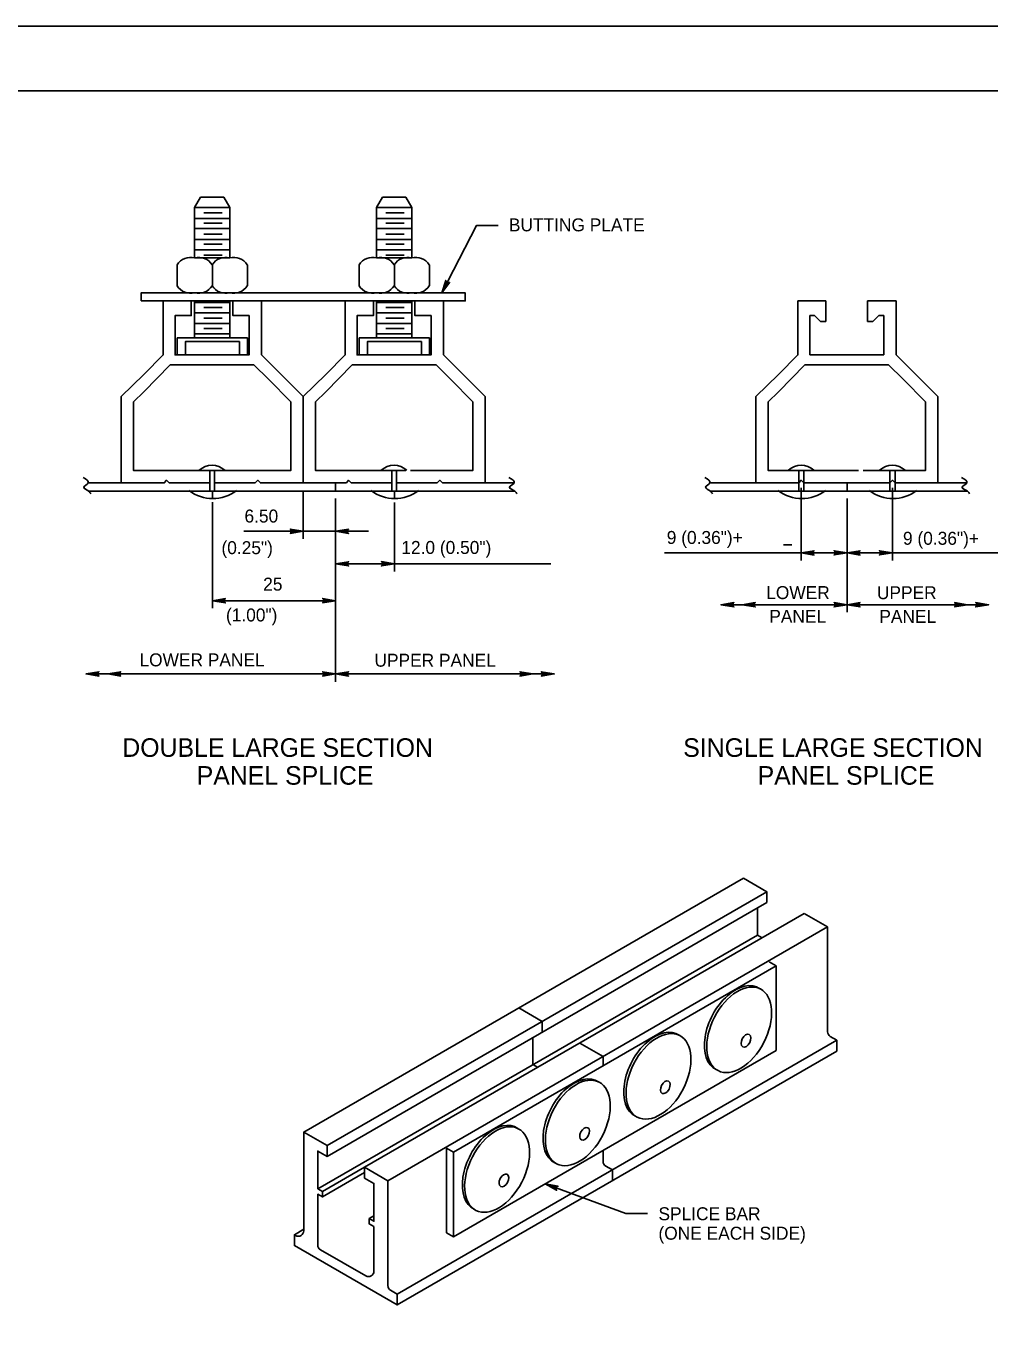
# Model space of a CAD drawing. Extents: x 650495 to 652241, y 298458 to 299646.
# Drawn here: x 651581.9 to 651805, y 299343.6 to 299645.6 of the extents above; entities that cross this region are included whole.
import ezdxf

# ---------------------------------------------------------------- set-up
doc = ezdxf.new("R2010")
doc.units = 0
for name, color, linetype in [('1', 7, 'Continuous'), ('2', 7, 'Continuous'), ('3', 7, 'Continuous'), ('PLT-BNDY', 7, 'Continuous')]:
    doc.layers.add(name, color=color, linetype=linetype)

# ---------------------------------------------------------------- blocks, each defined once
blk = doc.blocks.new('RARROW')
at = {"layer": '3'}
blk.add_lwpolyline([(-2.2695, 0.285), (-2.184875, 0.12075), (0, 0), (-2.2695, 0.285), (-2.38575, 0.384625), (0, 0), (-2.183125, -0.108), (-2.262875, -0.2705), (0, 0), (-2.38575, -0.379125), (-2.262875, -0.2705)], dxfattribs=at)

msp = doc.modelspace()

# ---------------------------------------------------------------- linework, layer by layer
at = {"layer": '1'}
msp.add_line((651376.31, 299630.63), (652162.31, 299630.63), dxfattribs=at)
at = {"layer": '2'}
for p, q in [((651620.9, 299603.62), (651622.28, 299606)), ((651622.28, 299606), (651627.65, 299606)), ((651629.03, 299603.62), (651627.65, 299606)), ((651663.03, 299603.62), (651664.4, 299606)), ((651664.4, 299606), (651669.78, 299606)), ((651671.15, 299603.62), (651669.78, 299606)), ((651620.9, 299603.62), (651629.03, 299603.62)), ((651620.9, 299603.62), (651620.9, 299601.12)), ((651620.9, 299592), (651620.9, 299603.62)), ((651629.03, 299592), (651629.03, 299603.62)), ((651663.03, 299603.62), (651671.15, 299603.62)), ((651663.03, 299603.62), (651663.03, 299601.12)), ((651663.03, 299592), (651663.03, 299603.62)), ((651671.15, 299592), (651671.15, 299603.62)), ((651620.9, 299601.12), (651629.03, 299601.12)), ((651623.03, 299602.37), (651627.28, 299602.37)), ((651623.03, 299600), (651627.28, 299600)), ((651663.03, 299601.12), (651671.15, 299601.12)), ((651665.15, 299602.37), (651669.4, 299602.37)), ((651665.15, 299600), (651669.4, 299600)), ((651620.9, 299598.75), (651629.03, 299598.75)), ((651623.03, 299597.5), (651627.28, 299597.5)), ((651663.03, 299598.75), (651671.15, 299598.75)), ((651665.15, 299597.5), (651669.4, 299597.5)), ((651620.9, 299596.25), (651629.03, 299596.25)), ((651620.9, 299593.87), (651629.03, 299593.87)), ((651623.03, 299595.12), (651627.28, 299595.12)), ((651663.03, 299596.25), (651671.15, 299596.25)), ((651663.03, 299593.87), (651671.15, 299593.87)), ((651665.15, 299595.12), (651669.4, 299595.12)), ((651616.9, 299585.5), (651616.9, 299590.37)), ((651620.9, 299592), (651629.03, 299592)), ((651629.03, 299592), (651620.9, 299592)), ((651623.03, 299592.62), (651627.28, 299592.62)), ((651625.03, 299590.37), (651625.03, 299585.5)), ((651633.15, 299585.5), (651633.15, 299590.37)), ((651659.03, 299585.5), (651659.03, 299590.37)), ((651663.03, 299592), (651671.15, 299592)), ((651671.15, 299592), (651663.03, 299592)), ((651665.15, 299592.62), (651669.4, 299592.62)), ((651667.15, 299590.37), (651667.15, 299585.5)), ((651675.28, 299585.5), (651675.28, 299590.37)), ((651629.03, 299583.87), (651620.9, 299583.87)), ((651620.9, 299573.5), (651620.9, 299582)), ((651620.9, 299581.62), (651629.03, 299581.62)), ((651629.03, 299573.5), (651629.03, 299582)), ((651671.15, 299583.87), (651663.03, 299583.87)), ((651663.03, 299573.5), (651663.03, 299582)), ((651663.03, 299581.62), (651671.15, 299581.62)), ((651671.15, 299573.5), (651671.15, 299582)), ((651760.53, 299571.12), (651760.53, 299582)), ((651760.53, 299582), (651767.03, 299582)), ((651767.03, 299582), (651767.03, 299577.25)), ((651776.66, 299577.25), (651776.66, 299582)), ((651776.66, 299582), (651783.28, 299582)), ((651783.28, 299582), (651783.28, 299572.25)), ((651620.9, 299579.25), (651629.03, 299579.25)), ((651623.03, 299580.5), (651627.28, 299580.5)), ((651663.03, 299579.25), (651671.15, 299579.25)), ((651665.15, 299580.5), (651669.4, 299580.5)), ((651763.28, 299578.62), (651764.41, 299578.62)), ((651763.28, 299578.62), (651763.28, 299569.5)), ((651765.78, 299577.25), (651764.41, 299578.62)), ((651777.91, 299577.25), (651779.28, 299578.62)), ((651780.41, 299578.62), (651779.28, 299578.62)), ((651780.41, 299569.5), (651780.41, 299578.62)), ((651620.9, 299576.75), (651629.03, 299576.75)), ((651623.03, 299578), (651627.28, 299578)), ((651623.03, 299575.62), (651627.28, 299575.62)), ((651663.03, 299576.75), (651671.15, 299576.75)), ((651665.15, 299578), (651669.4, 299578)), ((651665.15, 299575.62), (651669.4, 299575.62)), ((651765.78, 299577.25), (651767.03, 299577.25)), ((651777.91, 299577.25), (651776.66, 299577.25)), ((651616.9, 299569.5), (651616.9, 299573.5)), ((651616.9, 299573.5), (651633.15, 299573.5)), ((651620.9, 299574.37), (651629.03, 299574.37)), ((651633.15, 299573.5), (651633.15, 299569.5)), ((651659.03, 299569.5), (651659.03, 299573.5)), ((651659.03, 299573.5), (651675.28, 299573.5)), ((651663.03, 299574.37), (651671.15, 299574.37)), ((651675.28, 299573.5), (651675.28, 299569.5)), ((651633.15, 299569.5), (651616.9, 299569.5)), ((651675.28, 299569.5), (651659.03, 299569.5)), ((651763.28, 299569.5), (651780.41, 299569.5)), ((651624.4, 299538), (651624.4, 299542.75)), ((651625.53, 299538), (651625.53, 299542.75)), ((651666.53, 299538), (651666.53, 299542.75)), ((651667.65, 299538), (651667.65, 299542.75)), ((651760.78, 299538), (651760.78, 299542.75)), ((651761.91, 299538), (651761.91, 299542.75)), ((651781.78, 299538), (651781.78, 299542.75)), ((651783.03, 299538), (651783.03, 299542.75)), ((651603.9, 299539.87), (651596.28, 299539.87)), ((651653.53, 299539.87), (651653.53, 299538)), ((651688.15, 299539.87), (651694.9, 299539.87)), ((651740.16, 299539.87), (651750.78, 299539.87)), ((651771.28, 299539.87), (651772.41, 299539.87)), ((651771.91, 299539.87), (651771.91, 299538)), ((651792.91, 299539.87), (651799.66, 299539.87)), ((651596.28, 299538), (651695.03, 299538)), ((651625.03, 299538), (651625.03, 299536.26)), ((651646.03, 299538.12), (651646.03, 299526.93)), ((651653.53, 299536.25), (651653.53, 299493.86)), ((651666.53, 299538), (651667.65, 299538)), ((651667.15, 299538), (651667.15, 299536.26)), ((651740.28, 299538), (651799.78, 299538)), ((651760.78, 299538), (651761.91, 299538)), ((651761.28, 299538.75), (651761.28, 299521.95)), ((651771.28, 299538), (651772.41, 299538)), ((651771.91, 299536.25), (651771.91, 299509.95)), ((651781.78, 299538), (651783.03, 299538)), ((651782.41, 299538.75), (651782.41, 299521.95)), ((651625.03, 299535.41), (651625.03, 299510.88)), ((651667.15, 299535.36), (651667.15, 299519.41)), ((651646.03, 299528.68), (651632.28, 299528.68)), ((651661.12, 299528.68), (651646.03, 299528.68)), ((651757.17, 299525.58), (651759.16, 299525.58)), ((651653.53, 299521.16), (651703.34, 299521.16)), ((651729.65, 299523.7), (651814, 299523.7)), ((651782.41, 299523.7), (651782.41, 299523.7)), ((651625.03, 299512.63), (651653.53, 299512.63)), ((651743.17, 299511.7), (651771.91, 299511.7)), ((651771.91, 299511.7), (651803.33, 299511.7)), ((651653.53, 299495.68), (651595.78, 299495.68)), ((651653.53, 299495.68), (651704.13, 299495.68)), ((651646.16, 299389.62), (651747.92, 299448.37)), ((651651.57, 299386.49), (651753.33, 299445.24)), ((651651.57, 299383.99), (651753.33, 299442.74)), ((651660.24, 299381.49), (651761.99, 299440.24)), ((651665.65, 299378.37), (651767.41, 299437.12)), ((651649.41, 299376.49), (651751.17, 299435.24)), ((651753.87, 299429.02), (651755.5, 299428.08)), ((651751.72, 299422.82), (651751.72, 299422.82)), ((651667.81, 299352.12), (651769.57, 299410.87)), ((651733.05, 299412.04), (651733.05, 299412.04)), ((651667.81, 299349.62), (651769.57, 299408.37)), ((651755.5, 299408.52), (651755.5, 299408.52)), ((651741.62, 299404.1), (651741.62, 299404.1)), ((651714.38, 299401.26), (651714.38, 299401.26)), ((651736.82, 299397.74), (651736.82, 299397.74)), ((651722.95, 299393.32), (651722.95, 299393.32)), ((651646.16, 299389.62), (651646.16, 299389.62)), ((651695.7, 299390.48), (651695.7, 299390.48)), ((651679.18, 299385.89), (651679.18, 299366.33)), ((651679.18, 299385.89), (651680.8, 299384.95)), ((651718.15, 299386.96), (651718.15, 299386.96)), ((651704.28, 299382.54), (651704.28, 299382.54)), ((651650.49, 299375.87), (651660.24, 299381.49)), ((651650.49, 299374.62), (651660.24, 299380.24)), ((651699.48, 299376.17), (651699.48, 299376.17)), ((651661.32, 299369.62), (651662.4, 299370.24)), ((651685.6, 299371.76), (651685.6, 299371.76)), ((651644, 299365.87), (651646.16, 299367.12)), ((651680.8, 299365.39), (651679.18, 299366.33)), ((651680.8, 299365.39), (651680.8, 299365.39)), ((651650.03, 299362.38), (651660.53, 299356.33))]:
    msp.add_line(p, q, dxfattribs=at)
for points in [[(651691.15, 299599.5), (651686.15, 299599.5), (651678.09, 299583.87)], [(651613.65, 299571.12), (651613.65, 299582), (651620.15, 299582), (651620.15, 299578.62), (651616.4, 299578.62), (651616.4, 299571.12)], [(651633.53, 299572.25), (651633.53, 299578.62), (651629.78, 299578.62), (651629.78, 299582), (651636.4, 299582), (651636.4, 299572.25)], [(651655.78, 299571.12), (651655.78, 299582), (651662.28, 299582), (651662.28, 299578.62), (651658.53, 299578.62), (651658.53, 299571.12)], [(651675.65, 299572.25), (651675.65, 299578.62), (651671.9, 299578.62), (651671.9, 299582), (651678.53, 299582), (651678.53, 299572.25)], [(651628.78, 299569.5), (651633.53, 299569.5), (651633.53, 299572.25)], [(651636.4, 299572.25), (651636.4, 299569.5), (651642.03, 299563.87)], [(651670.9, 299569.5), (651675.65, 299569.5), (651675.65, 299572.25)], [(651678.53, 299572.25), (651678.53, 299569.5), (651684.15, 299563.87)], [(651783.28, 299572.25), (651783.28, 299569.5), (651788.91, 299563.87)], [(651609.15, 299565), (651613.65, 299569.5), (651613.65, 299571.12)], [(651616.4, 299571.12), (651616.4, 299569.5), (651623.78, 299569.5)], [(651623.78, 299569.5), (651625.03, 299569.5)], [(651625.03, 299569.5), (651628.78, 299569.5)], [(651651.28, 299565), (651655.78, 299569.5), (651655.78, 299571.12)], [(651658.53, 299571.12), (651658.53, 299569.5), (651665.9, 299569.5)], [(651665.9, 299569.5), (651667.15, 299569.5)], [(651667.15, 299569.5), (651670.9, 299569.5)], [(651756.03, 299565), (651760.53, 299569.5), (651760.53, 299571.12)], [(651771.91, 299569.5), (651775.66, 299569.5)], [(651615.28, 299567.25), (651609.15, 299561)], [(651623.78, 299567.25), (651615.28, 299567.25)], [(651625.03, 299567.25), (651623.78, 299567.25)], [(651628.78, 299567.25), (651625.03, 299567.25)], [(651634.65, 299567.25), (651628.78, 299567.25)], [(651638.03, 299563.87), (651634.65, 299567.25)], [(651657.4, 299567.25), (651651.28, 299561)], [(651665.9, 299567.25), (651657.4, 299567.25)], [(651667.15, 299567.25), (651665.9, 299567.25)], [(651670.9, 299567.25), (651667.15, 299567.25)], [(651676.78, 299567.25), (651670.9, 299567.25)], [(651680.15, 299563.87), (651676.78, 299567.25)], [(651762.16, 299567.25), (651756.03, 299561)], [(651770.66, 299567.25), (651762.16, 299567.25)], [(651771.91, 299567.25), (651770.66, 299567.25)], [(651775.66, 299567.25), (651771.91, 299567.25)], [(651781.53, 299567.25), (651775.66, 299567.25)], [(651784.91, 299563.87), (651781.53, 299567.25)], [(651609.15, 299539.87), (651603.9, 299539.87), (651603.9, 299559.87), (651609.15, 299565)], [(651643.15, 299549.62), (651643.15, 299558.62), (651638.03, 299563.87)], [(651642.03, 299563.87), (651646.03, 299559.87), (651646.03, 299549.62)], [(651651.28, 299539.87), (651646.03, 299539.87), (651646.03, 299559.87), (651651.28, 299565)], [(651685.28, 299549.62), (651685.28, 299558.62), (651680.15, 299563.87)], [(651684.15, 299563.87), (651688.15, 299559.87), (651688.15, 299549.62)], [(651756.03, 299539.87), (651750.78, 299539.87), (651750.78, 299559.87), (651756.03, 299565)], [(651790.03, 299549.62), (651790.03, 299558.62), (651784.91, 299563.87)], [(651788.91, 299563.87), (651792.91, 299559.87), (651792.91, 299549.62)], [(651609.15, 299561), (651606.78, 299558.62), (651606.78, 299542.75), (651609.15, 299542.75)], [(651651.28, 299561), (651648.9, 299558.62), (651648.9, 299542.75), (651651.28, 299542.75)], [(651756.03, 299561), (651753.66, 299558.62), (651753.66, 299542.75), (651756.03, 299542.75)], [(651628.78, 299542.75), (651643.15, 299542.75), (651643.15, 299549.62)], [(651646.03, 299549.62), (651646.03, 299539.87), (651636.15, 299539.87), (651635.53, 299540.5), (651634.9, 299539.87), (651628.78, 299539.87)], [(651670.9, 299542.75), (651685.28, 299542.75), (651685.28, 299549.62)], [(651688.15, 299549.62), (651688.15, 299539.87), (651678.28, 299539.87), (651677.65, 299540.5), (651677.03, 299539.87), (651670.9, 299539.87)], [(651775.66, 299542.75), (651790.03, 299542.75), (651790.03, 299549.62)], [(651792.91, 299549.62), (651792.91, 299539.87), (651783.03, 299539.87), (651782.41, 299540.5), (651781.78, 299539.87), (651775.66, 299539.87)], [(651609.15, 299542.75), (651625.03, 299542.75)], [(651625.03, 299542.75), (651627.65, 299542.75)], [(651627.65, 299542.75), (651628.78, 299542.75)], [(651651.28, 299542.75), (651667.15, 299542.75)], [(651667.15, 299542.75), (651669.78, 299542.75)], [(651756.03, 299542.75), (651771.91, 299542.75)], [(651771.91, 299542.75), (651774.53, 299542.75)], [(651609.15, 299539.87), (651603.9, 299539.87)], [(651609.15, 299539.87), (651613.9, 299539.87), (651614.4, 299540.5), (651615.03, 299539.87), (651624.4, 299539.87)], [(651624.4, 299539.87), (651615.03, 299539.87), (651614.4, 299540.5), (651613.9, 299539.87), (651609.15, 299539.87)], [(651625.53, 299539.87), (651627.65, 299539.87)], [(651627.65, 299539.87), (651625.53, 299539.87)], [(651628.78, 299539.87), (651627.65, 299539.87)], [(651628.78, 299539.87), (651627.65, 299539.87)], [(651628.78, 299539.87), (651634.9, 299539.87), (651635.53, 299540.5), (651636.15, 299539.87), (651646.03, 299539.87)], [(651651.28, 299539.87), (651646.03, 299539.87)], [(651651.28, 299539.87), (651656.03, 299539.87), (651656.53, 299540.5), (651657.15, 299539.87), (651666.53, 299539.87)], [(651666.53, 299539.87), (651657.15, 299539.87), (651656.53, 299540.5), (651656.03, 299539.87), (651651.28, 299539.87)], [(651667.65, 299539.87), (651669.78, 299539.87)], [(651667.65, 299539.87), (651669.78, 299539.87)], [(651669.78, 299539.87), (651667.65, 299539.87)], [(651670.9, 299539.87), (651669.78, 299539.87)], [(651670.9, 299539.87), (651669.78, 299539.87)], [(651670.9, 299539.87), (651669.78, 299539.87)], [(651670.9, 299539.87), (651677.03, 299539.87), (651677.65, 299540.5), (651678.28, 299539.87), (651688.15, 299539.87)], [(651756.03, 299539.87), (651750.78, 299539.87)], [(651771.28, 299539.87), (651761.91, 299539.87), (651761.28, 299540.5), (651760.78, 299539.87), (651756.03, 299539.87)], [(651774.53, 299539.87), (651772.41, 299539.87)], [(651775.66, 299539.87), (651774.53, 299539.87)], [(651747.92, 299448.37), (651753.33, 299445.24), (651753.33, 299442.74)], [(651751.17, 299441.49), (651751.17, 299435.24), (651752.25, 299434.62)], [(651761.99, 299440.24), (651767.41, 299437.12), (651767.41, 299412.84)], [(651680.8, 299384.95), (651755.5, 299428.08), (651755.5, 299408.52), (651680.8, 299365.39), (651680.8, 299384.95)], [(651695.96, 299418.37), (651701.37, 299415.24), (651701.37, 299412.74)], [(651699.21, 299411.49), (651699.21, 299405.24), (651700.29, 299404.62)], [(651710.03, 299410.24), (651715.44, 299407.12), (651715.44, 299404.95)], [(651768.03, 299411.76), (651769.57, 299410.87), (651769.57, 299408.37)], [(651646.16, 299366.78), (651646.16, 299389.62), (651651.57, 299386.49), (651651.57, 299383.99), (651649.41, 299385.24), (651649.41, 299376.49), (651650.49, 299375.87), (651650.49, 299374.62), (651649.41, 299375.24), (651649.41, 299363.47)], [(651715.44, 299385.39), (651715.44, 299382.84)], [(651662.4, 299357.41), (651662.4, 299367.74), (651661.32, 299368.37), (651661.32, 299369.62), (651662.4, 299368.99), (651662.4, 299377.74), (651660.24, 299378.99), (651660.24, 299381.49), (651665.65, 299378.37), (651665.65, 299354.09)], [(651716.07, 299381.76), (651717.61, 299380.87), (651717.61, 299378.37)], [(651725.71, 299370.81), (651720.71, 299370.81), (651702.03, 299377.65)], [(651666.27, 299353.01), (651667.81, 299352.12), (651667.81, 299349.62), (651644, 299363.37), (651644, 299365.87), (651644.29, 299365.7)]]:
    msp.add_lwpolyline(points, dxfattribs=at)
for points in [[(651608.53, 299582), (651608.53, 299583.87), (651683.53, 299583.87), (651683.53, 299582)], [(651631.28, 299569.5), (651631.28, 299572.62), (651618.78, 299572.62), (651618.78, 299569.5)], [(651673.4, 299569.5), (651673.4, 299572.62), (651660.9, 299572.62), (651660.9, 299569.5)]]:
    msp.add_lwpolyline(points, close=True, dxfattribs=at)
for centre, radius, start, end in [((651620.04, 299588.31), 3.8, 76.6866, 146.9162), ((651621.79, 299588.31), 3.8, 33.0838, 103.3134), ((651628.17, 299588.31), 3.8, 76.6866, 146.9162), ((651629.92, 299588.31), 3.8, 33.0838, 103.3134), ((651662.16, 299588.31), 3.8, 76.6866, 146.9162), ((651663.92, 299588.31), 3.8, 33.0838, 103.3134), ((651670.29, 299588.31), 3.8, 76.6866, 146.9162), ((651672.04, 299588.31), 3.8, 33.0838, 103.3134), ((651620.04, 299587.58), 3.8, 213.0838, 283.3134), ((651621.79, 299587.58), 3.8, 256.6866, 326.9162), ((651628.17, 299587.58), 3.8, 213.0838, 283.3134), ((651629.92, 299587.58), 3.8, 256.6866, 326.9162), ((651662.16, 299587.58), 3.8, 213.0838, 283.3134), ((651663.92, 299587.58), 3.8, 256.6866, 326.9162), ((651670.29, 299587.58), 3.8, 213.0838, 283.3134), ((651672.04, 299587.58), 3.8, 256.6866, 326.9162), ((651624.95, 299539.77), 4.23, 45.7805, 134.2195), ((651667.07, 299539.77), 4.23, 45.7805, 134.2195), ((651761.28, 299539.77), 4.23, 45.7805, 134.2195), ((651782.37, 299539.77), 4.23, 45.7805, 134.2195), ((651625.11, 299545.27), 9.01, 232.6949, 307.3051), ((651667.23, 299545.27), 9.01, 232.6949, 307.3051), ((651761.44, 299545.27), 9.01, 232.6949, 307.3051), ((651782.53, 299545.27), 9.01, 232.6949, 307.3051), ((651768.66, 299412.84), 1.25, 180, 239.9993), ((651716.69, 299382.84), 1.25, 180, 239.9993), ((651644.91, 299366.78), 1.25, 239.9993, 0), ((651650.66, 299363.47), 1.25, 180, 240.0002), ((651661.15, 299357.41), 1.25, 239.9999, 0), ((651666.9, 299354.09), 1.25, 180, 239.9993)]:
    msp.add_arc(centre, radius, start, end, dxfattribs=at)
for centre, major_axis in [((651746.94, 299413.3), (4.9, 9.45)), ((651728.27, 299402.52), (4.9, 9.45)), ((651748.52, 299410.78), (0.74, 1.42)), ((651709.6, 299391.74), (4.9, 9.45)), ((651729.85, 299400), (0.74, 1.42)), ((651690.92, 299380.96), (4.9, 9.45)), ((651711.17, 299389.22), (0.74, 1.42)), ((651692.5, 299378.44), (0.74, 1.42))]:
    msp.add_ellipse(centre, major_axis=major_axis, ratio=0.602781, dxfattribs=at)
for centre in [(651746.4, 299413.62), (651727.73, 299402.83), (651709.06, 299392.05), (651690.38, 299381.27)]:
    msp.add_ellipse(centre, major_axis=(4.9, 9.45), ratio=0.602781, start_param=6.207238, end_param=9.446163, dxfattribs=at)
for points in [[(651595.15, 299541.12), (651596.28, 299539.87), (651595.28, 299538.87), (651596.4, 299538), (651596.9, 299537.37)], [(651693.65, 299541.12), (651694.9, 299539.87), (651693.78, 299538.87), (651695.03, 299538), (651695.53, 299537.37)], [(651739.03, 299541.12), (651740.16, 299539.87), (651739.16, 299538.87), (651740.28, 299538), (651740.78, 299537.37)], [(651798.41, 299541.12), (651799.66, 299539.87), (651798.53, 299538.87), (651799.78, 299538), (651800.28, 299537.37)]]:
    msp.add_spline(points, degree=3, dxfattribs=at)
at = {"layer": 'PLT-BNDY'}
msp.add_lwpolyline([(651336.31, 299645.63), (652177.31, 299645.63), (652177.31, 299051.63), (651336.31, 299051.63)], close=True, dxfattribs=at)

# ---------------------------------------------------------------- block references
at = {"layer": '2', "xscale": 1.2574347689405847}
for p, yscale, rotation in [((651678.09, 299583.87), 1.3092961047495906, -117.30666422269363), ((651653.53, 299528.68), 1.3092961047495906, 180), ((651761.28, 299523.7), 1.3092961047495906, 180), ((651771.91, 299523.7), 1.3092961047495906, 180), ((651653.53, 299521.16), 1.3092961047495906, 180), ((651625.03, 299512.63), 1.3092961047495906, 180), ((651742.71, 299511.7), -1.3092961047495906, -180), ((651747.66, 299511.7), 1.3092961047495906, 180), ((651771.91, 299511.7), 1.3092961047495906, 180), ((651595.78, 299495.68), 1.3092961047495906, 180), ((651600.83, 299495.68), -1.3092961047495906, -180), ((651653.53, 299495.68), 1.3092961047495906, 180), ((651702.03, 299377.65), 1.3092961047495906, 159.89547322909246)]:
    msp.add_blockref('RARROW', p, dxfattribs=dict(at, yscale=yscale, rotation=rotation))
for p, yscale in [((651646.03, 299528.68), 1.3092961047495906), ((651771.91, 299523.7), 1.3092961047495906), ((651782.41, 299523.7), 1.3092961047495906), ((651667.15, 299521.16), 1.3092961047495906), ((651653.53, 299512.63), 1.3092961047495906), ((651771.91, 299511.7), 1.3092961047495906), ((651799.78, 299511.7), 1.3092961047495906), ((651804.68, 299511.7), -1.3092961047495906), ((651653.53, 299495.68), 1.3092961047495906), ((651699.2, 299495.68), 1.3092961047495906), ((651704.13, 299495.68), 1.3092961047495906)]:
    msp.add_blockref('RARROW', p, dxfattribs=dict(at, yscale=yscale))

# ---------------------------------------------------------------- texts
at = {"layer": '2'}
for s, height, p in [('BUTTING PLATE', 2.9992, (651693.65, 299598.12)), ('6.50 ', 3, (651632.45, 299530.72)), ('9 (0.36")+', 3, (651730.18, 299525.76)), ('9 (0.36")+', 3, (651784.85, 299525.57)), (' (0.25")', 3, (651626.01, 299523.4)), ('12.0 (0.50")', 3, (651668.75, 299523.45)), ('25', 3, (651636.78, 299514.96)), ('LOWER', 2.999, (651753.2, 299513)), ('UPPER', 2.999, (651778.82, 299512.98)), (' (1.00")', 3, (651627.05, 299507.82)), ('PANEL', 2.999, (651753.91, 299507.51)), ('PANEL', 2.999, (651779.38, 299507.49)), ('LOWER PANEL', 2.9992, (651608.15, 299497.43)), ('UPPER PANEL', 2.9992, (651662.53, 299497.34)), ('DOUBLE LARGE SECTION', 4.3, (651604.17, 299476.48)), ('SINGLE LARGE SECTION', 4.3, (651733.99, 299476.48)), ('PANEL SPLICE', 4.3, (651621.39, 299470.03)), ('PANEL SPLICE', 4.3, (651751.21, 299470.03))]:
    msp.add_text(s, height=height, dxfattribs=at).set_placement(p)
at = {"layer": '3'}
for s, p in [('SPLICE BAR', (651728.26, 299369.22)), ('(ONE EACH SIDE)', (651728.26, 299364.72))]:
    msp.add_text(s, height=3, dxfattribs=at).set_placement(p)

doc.saveas('drawing.dxf')
